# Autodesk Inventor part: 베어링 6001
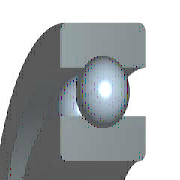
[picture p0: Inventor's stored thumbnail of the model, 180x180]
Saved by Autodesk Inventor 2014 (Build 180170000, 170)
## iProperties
Created: 2012-02
Part Number: 베어링 6001
Material: 강철, 연강
Description: 깊은 그루브 볼 베어링
Document SubType Name: Modeling
Standard: KS B 2023
Designer: mduedu
Standards Organization: KS
Language: ko-KR
Size Designation: 6001 - 12 x 28 x 8
Categories: <MemberInstance><Categories><Category DisplayName="샤프트 부품" InternalName="7f7aeb1f-a693-4053-b835-cee3144e0d98" Mnemonic="SHFT"><Category DisplayName="베어링" Inter
Density: 7.86 g/cm^3
Mass: 19.7077 g
Surface Area: 31.1809 cm^2
Volume: 2.50734 cm^3
Appearance: 노란색
IsCustomPart: 1
Author: mduedu
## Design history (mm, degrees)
sketch "스케치" dims "d0" = 4.16 (= -0.26 x WD + 0.26 x BD)
  geometry: L1 (1.92, 10)-(6.08, 10); L2 (4, 10)-(4, 7.92); L3 (4, 10)-(4, 12.08); L4 (2.454, 8.608)-(0, 8.608); L5 (0, 6)-(8, 6); L6 (2.454, 11.392)-(0, 11.392); L7 (0, 14)-(8, 14); L8 (8, 6)-(8, 8.608); L9 (5.546, 8.608)-(8, 8.608); L10 (5.546, 11.392)-(8, 11.392); L11 (8, 14)-(8, 11.392); L12 (-1.4, 0)-(8.4, 0) reference; L13 (0, -0.3)-(0, 5.3) reference
  constraints: 22 end point, 4 point on line, 2 collinear, 2 perpendicular, 2 symmetric about line, 1 midpoint, 1 parallel, 14 other
  dimensions: "d9" = 12 diameter of L5 L12 (= WD); "d11" = 28 diameter of L7 L12 (= BD); "d12" = 8 distance between parallel lines of L8 L13 (= KB); "d13" = 17.216 diameter of L9 L12 (= 0.326 x BD + 0.674 x WD)
revolve "본체" stored, may be unused: angle "d6" = 90 deg
revolve "볼" stored, may be unused: angle "d7" = 90 deg
pattern_circular "IDS_ARRAYBALL[SIMPL:T]" dims angle "d3" = 360 deg
body "Solid1"
fillet "모깎기1" dims "d1" = 0.3 (= KRS)
other parameters: "WD" = 12 [user parameter; used in 5 equation terms], "BD" = 28 [user parameter; used in 5 equation terms], "KB" = 8 [user parameter; used in 1 equation term], "KRS" = 0.3 [user parameter; used in 1 equation term], "d4" = 0, "d5" = 0, "d8" = 0, "d14" = 0, "d15" = 0, "BBA" = 0 [user parameter], "BC0" = 2360000 [user parameter], "BC" = 5070000 [user parameter], "BR" = 14 (= 0.5 x BD) [user parameter], "WR" = 6 (= 0.5 x WD) [user parameter]
